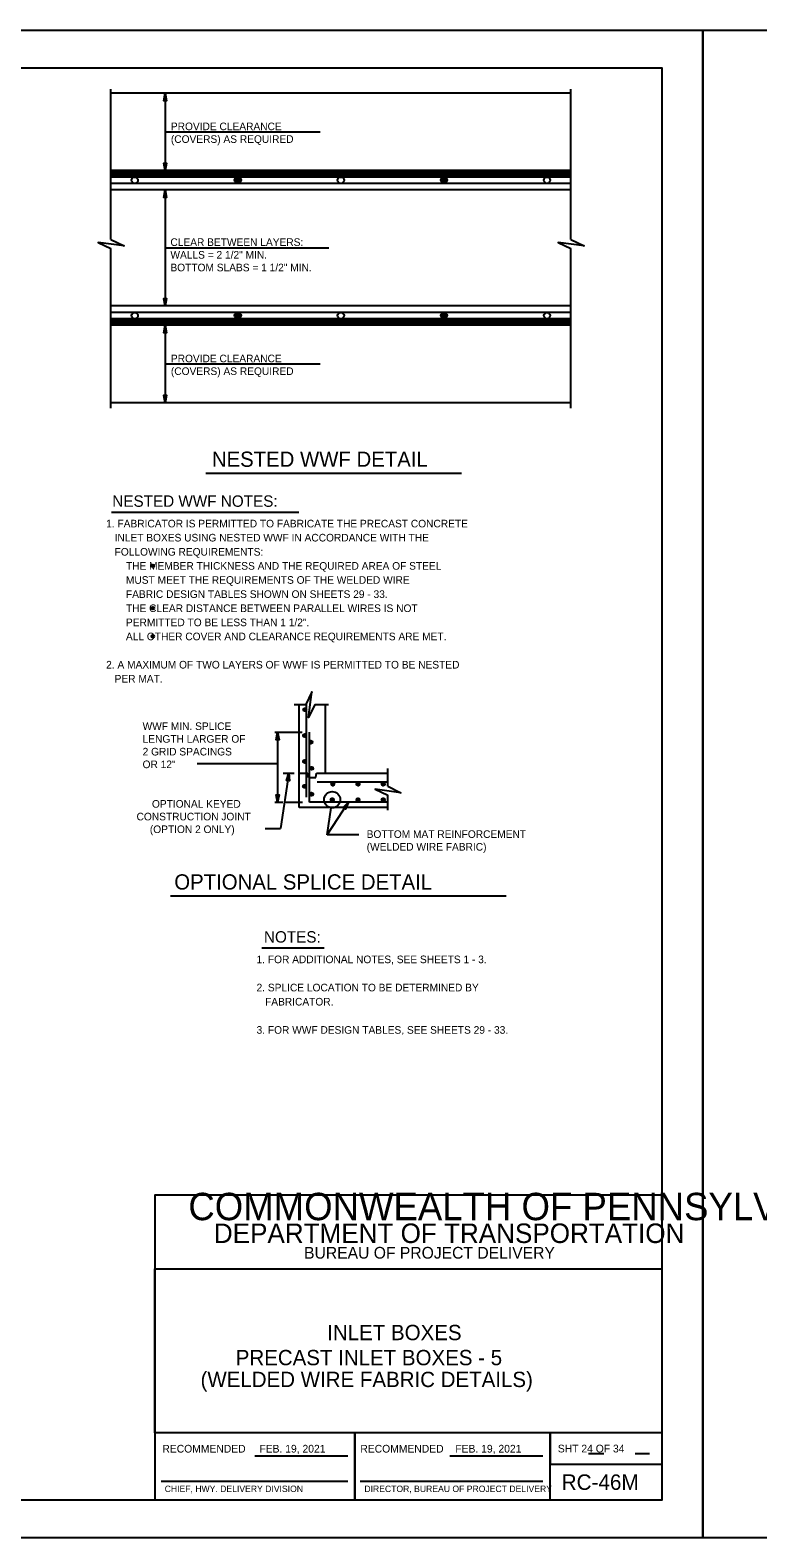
# Model space of a CAD drawing. Extents: x -6420 to 49575, y -4552 to 11624.
# Drawn here: x 6505 to 7447, y 1880 to 3829 of the extents above; entities that cross this region are included whole.
import ezdxf

# ---------------------------------------------------------------- set-up
doc = ezdxf.new("R2010")
doc.units = 0
doc.layers.add('1', color=7, linetype='Continuous')
doc.layers.add('PLT-BNDY', color=7, linetype='Continuous')

msp = doc.modelspace()

# ---------------------------------------------------------------- linework, layer by layer
at = {"layer": '1'}
for p, q in [((6609.9, 3558), (6609.9, 3752.3)), ((7204.9, 3747.1), (6609.9, 3747.1)), ((6680, 3747.1), (6680, 3647.1)), ((7204.9, 3558), (7204.9, 3752.3)), ((6680, 3697.1), (6880.5, 3697.1)), ((7204.9, 3647.1), (6609.9, 3647.1)), ((7204.9, 3645.7), (6609.9, 3645.7)), ((7204.9, 3644.4), (6609.9, 3644.4)), ((7204.9, 3643), (6609.9, 3643)), ((7204.9, 3641.7), (6609.9, 3641.7)), ((7204.9, 3640.3), (6609.9, 3640.3)), ((7204.9, 3638.8), (6609.9, 3638.8)), ((7204.9, 3630.5), (6609.9, 3630.5)), ((7204.9, 3622.1), (6609.9, 3622.1)), ((6680, 3622.1), (6680, 3472.1)), ((6680, 3547.1), (6891.7, 3547.1)), ((6609.9, 3340.1), (6609.9, 3546.5)), ((7204.9, 3340.1), (7204.9, 3546.5)), ((7204.9, 3472.1), (6609.9, 3472.1)), ((7204.9, 3463.7), (6609.9, 3463.7)), ((7204.9, 3455.4), (6609.9, 3455.4)), ((7204.9, 3453.9), (6609.9, 3453.9)), ((7204.9, 3452.5), (6609.9, 3452.5)), ((7204.9, 3451.2), (6609.9, 3451.2)), ((7204.9, 3449.8), (6609.9, 3449.8)), ((7204.9, 3448.5), (6609.9, 3448.5)), ((7204.9, 3447.1), (6609.9, 3447.1)), ((6680, 3447.1), (6680, 3347.1)), ((6680, 3397.1), (6880.5, 3397.1)), ((7204.9, 3347.1), (6609.9, 3347.1)), ((6732.5, 3255.9), (7063.6, 3255.9)), ((6610.7, 3205.7), (6853, 3205.7)), ((6847.1, 2957.1), (6862.2, 2957.1)), ((6853.6, 2823.7), (6853.6, 2957.1)), ((6863, 2837), (6863, 2958.8)), ((6873.7, 2957.1), (6891.3, 2957.1)), ((6886.9, 2957.1), (6886.9, 2868.2)), ((6822.1, 2921.3), (6857.3, 2921.3)), ((6825.5, 2921.3), (6825.5, 2830.6)), ((6867, 2830.6), (6867, 2921.3)), ((6721.6, 2880.9), (6825.5, 2880.9)), ((6840.2, 2868.2), (6829.3, 2796.5)), ((6832.9, 2868.2), (6847.2, 2868.2)), ((6853.5, 2868.2), (6864.7, 2868.2)), ((6865.4, 2862.6), (6864.7, 2868.2)), ((6875.1, 2862.6), (6875.8, 2868.2)), ((6875.8, 2868.2), (6886.9, 2868.2)), ((6886.9, 2868.2), (6968.2, 2868.2)), ((6968.2, 2851.3), (6968.2, 2874.4)), ((6865.4, 2862.6), (6875.1, 2862.6)), ((6876.9, 2857), (6968.2, 2857)), ((6822.1, 2830.6), (6832.3, 2830.6)), ((6836.2, 2830.6), (6857.8, 2830.6)), ((6968.2, 2830.6), (6867, 2830.6)), ((6889.6, 2788.6), (6917.2, 2830.6)), ((6896.2, 2833.9), (6896.2, 2833.9)), ((6968.2, 2820.2), (6968.2, 2839.8)), ((6968.2, 2823.7), (6853.6, 2823.7)), ((6889.6, 2788.6), (6894.8, 2823.5)), ((6809.3, 2796.5), (6829.3, 2796.5)), ((6930.8, 2788.6), (6889.6, 2788.6)), ((6686.8, 2709.5), (7121.4, 2709.5)), ((6805.3, 2642.4), (6885.7, 2642.4)), ((7227.6, 1988.7), (7247.7, 1988.7)), ((7288, 1988.7), (7306.8, 1988.7)), ((6795.9, 1986), (6916.3, 1986)), ((7048.5, 1986), (7168.9, 1986)), ((6674.8, 1953), (6916.3, 1953)), ((6932.4, 1953), (7168.9, 1953))]:
    msp.add_line(p, q, dxfattribs=at)
for points in [[(7323.1, 1929), (7323.1, 3779.4), (4744.3, 3779.4), (4744.3, 1929), (7323.1, 1929), (7323.1, 2015.5), (6666.9, 2015.5), (6666.9, 2227.7), (7323.1, 2227.7), (7323.1, 2322.7), (6666.9, 2322.7), (6666.9, 1929), (6925.4, 1929), (6925.4, 2015.5), (6925.4, 1929), (7178.1, 1929), (7178.1, 2015.5), (7178.1, 1975.1), (7323.1, 1975.1)], [(6680, 3747.1), (6681.9, 3737.3), (6681.6, 3737.7), (6681.3, 3738.1), (6681, 3738.3), (6680.7, 3738.5), (6680.4, 3738.5), (6680, 3738.6), (6679.7, 3738.5), (6679.4, 3738.5), (6679, 3738.3), (6678.7, 3738.1), (6678.5, 3737.7), (6678.2, 3737.3), (6680, 3747.1), (6678.5, 3737.7), (6678.7, 3738.1), (6680, 3747.1), (6679, 3738.3), (6679.4, 3738.5), (6680, 3747.1), (6679.7, 3738.5), (6680, 3738.6), (6680, 3747.1), (6680.4, 3738.5), (6680.7, 3738.5), (6680, 3747.1), (6681, 3738.3), (6681.3, 3738.1), (6680, 3747.1), (6681.6, 3737.7)], [(6680, 3647.1), (6678.2, 3656.9), (6678.5, 3656.5), (6678.7, 3656.1), (6679, 3655.9), (6679.4, 3655.7), (6679.7, 3655.7), (6680, 3655.6), (6680.4, 3655.7), (6680.7, 3655.7), (6681, 3655.9), (6681.3, 3656.1), (6681.6, 3656.5), (6681.9, 3656.9), (6680, 3647.1), (6681.6, 3656.5), (6681.3, 3656.1), (6680, 3647.1), (6681, 3655.9), (6680.7, 3655.7), (6680, 3647.1), (6680.4, 3655.7), (6680, 3655.6), (6680, 3647.1), (6679.7, 3655.7), (6679.4, 3655.7), (6680, 3647.1), (6679, 3655.9), (6678.7, 3656.1), (6680, 3647.1), (6678.5, 3656.5)], [(6680, 3622.1), (6681.9, 3612.4), (6681.6, 3612.7), (6681.3, 3613.1), (6681, 3613.3), (6680.7, 3613.5), (6680.4, 3613.6), (6680, 3613.6), (6679.7, 3613.6), (6679.4, 3613.5), (6679, 3613.3), (6678.7, 3613.1), (6678.5, 3612.7), (6678.2, 3612.4), (6680, 3622.1), (6678.5, 3612.7), (6678.7, 3613.1), (6680, 3622.1), (6679, 3613.3), (6679.4, 3613.5), (6680, 3622.1), (6679.7, 3613.6), (6680, 3613.6), (6680, 3622.1), (6680.4, 3613.6), (6680.7, 3613.5), (6680, 3622.1), (6681, 3613.3), (6681.3, 3613.1), (6680, 3622.1), (6681.6, 3612.7)], [(6609.9, 3558), (6626.9, 3549.7), (6593.6, 3554.2), (6609.9, 3546.5)], [(7204.9, 3558), (7222, 3549.7), (7188.7, 3554.2), (7204.9, 3546.5)], [(6680, 3472.1), (6678.2, 3481.8), (6678.5, 3481.5), (6678.7, 3481.1), (6679, 3480.9), (6679.4, 3480.7), (6679.7, 3480.6), (6680, 3480.6), (6680.4, 3480.6), (6680.7, 3480.7), (6681, 3480.9), (6681.3, 3481.1), (6681.6, 3481.5), (6681.9, 3481.8), (6680, 3472.1), (6681.6, 3481.5), (6681.3, 3481.1), (6680, 3472.1), (6681, 3480.9), (6680.7, 3480.7), (6680, 3472.1), (6680.4, 3480.6), (6680, 3480.6), (6680, 3472.1), (6679.7, 3480.6), (6679.4, 3480.7), (6680, 3472.1), (6679, 3480.9), (6678.7, 3481.1), (6680, 3472.1), (6678.5, 3481.5)], [(6680, 3447.1), (6681.9, 3437.3), (6681.6, 3437.7), (6681.3, 3438.1), (6681, 3438.3), (6680.7, 3438.5), (6680.4, 3438.5), (6680, 3438.6), (6679.7, 3438.5), (6679.4, 3438.5), (6679, 3438.3), (6678.7, 3438.1), (6678.5, 3437.7), (6678.2, 3437.3), (6680, 3447.1), (6678.5, 3437.7), (6678.7, 3438.1), (6680, 3447.1), (6679, 3438.3), (6679.4, 3438.5), (6680, 3447.1), (6679.7, 3438.5), (6680, 3438.6), (6680, 3447.1), (6680.4, 3438.5), (6680.7, 3438.5), (6680, 3447.1), (6681, 3438.3), (6681.3, 3438.1), (6680, 3447.1), (6681.6, 3437.7)], [(6680, 3347.1), (6678.2, 3356.9), (6678.5, 3356.5), (6678.7, 3356.1), (6679, 3355.9), (6679.4, 3355.7), (6679.7, 3355.7), (6680, 3355.6), (6680.4, 3355.7), (6680.7, 3355.7), (6681, 3355.9), (6681.3, 3356.1), (6681.6, 3356.5), (6681.9, 3356.9), (6680, 3347.1), (6681.6, 3356.5), (6681.3, 3356.1), (6680, 3347.1), (6681, 3355.9), (6680.7, 3355.7), (6680, 3347.1), (6680.4, 3355.7), (6680, 3355.6), (6680, 3347.1), (6679.7, 3355.7), (6679.4, 3355.7), (6680, 3347.1), (6679, 3355.9), (6678.7, 3356.1), (6680, 3347.1), (6678.5, 3356.5)], [(6873.7, 2957.1), (6865.4, 2940.1), (6869.9, 2973.4), (6862.2, 2957.1)], [(6825.5, 2921.3), (6827.4, 2911.5), (6827.1, 2911.8), (6826.8, 2912.2), (6826.5, 2912.4), (6826.2, 2912.6), (6825.8, 2912.7), (6825.5, 2912.7), (6825.2, 2912.7), (6824.9, 2912.6), (6824.5, 2912.4), (6824.2, 2912.2), (6823.9, 2911.8), (6823.7, 2911.5), (6825.5, 2921.3), (6823.9, 2911.8), (6824.2, 2912.2), (6825.5, 2921.3), (6824.5, 2912.4), (6824.9, 2912.6), (6825.5, 2921.3), (6825.2, 2912.7), (6825.5, 2912.7), (6825.5, 2921.3), (6825.8, 2912.7), (6826.2, 2912.6), (6825.5, 2921.3), (6826.5, 2912.4), (6826.8, 2912.2), (6825.5, 2921.3), (6827.1, 2911.8)], [(6840.2, 2868.2), (6840.8, 2858.3), (6840.6, 2858.7), (6840.4, 2859.1), (6840.1, 2859.3), (6839.8, 2859.6), (6839.5, 2859.7), (6839.1, 2859.8), (6838.8, 2859.8), (6838.5, 2859.7), (6838.1, 2859.6), (6837.8, 2859.4), (6837.5, 2859.1), (6837.2, 2858.8), (6840.2, 2868.2), (6837.5, 2859.1), (6837.8, 2859.4), (6840.2, 2868.2), (6838.1, 2859.6), (6838.5, 2859.7), (6840.2, 2868.2), (6838.8, 2859.8), (6839.1, 2859.8), (6840.2, 2868.2), (6839.5, 2859.7), (6839.8, 2859.6), (6840.2, 2868.2), (6840.1, 2859.3), (6840.4, 2859.1), (6840.2, 2868.2), (6840.6, 2858.7)], [(6968.2, 2851.3), (6985.2, 2843), (6951.9, 2847.5), (6968.2, 2839.8)], [(6825.5, 2830.6), (6823.7, 2840.4), (6823.9, 2840), (6824.2, 2839.6), (6824.5, 2839.4), (6824.9, 2839.2), (6825.2, 2839.2), (6825.5, 2839.1), (6825.8, 2839.2), (6826.2, 2839.2), (6826.5, 2839.4), (6826.8, 2839.6), (6827.1, 2840), (6827.4, 2840.4), (6825.5, 2830.6), (6827.1, 2840), (6826.8, 2839.6), (6825.5, 2830.6), (6826.5, 2839.4), (6826.2, 2839.2), (6825.5, 2830.6), (6825.8, 2839.2), (6825.5, 2839.1), (6825.5, 2830.6), (6825.2, 2839.2), (6824.9, 2839.2), (6825.5, 2830.6), (6824.5, 2839.4), (6824.2, 2839.6), (6825.5, 2830.6), (6823.9, 2840)], [(6917.2, 2830.6), (6913.2, 2821.5), (6913.2, 2821.9), (6913.2, 2822.4), (6913.1, 2822.7), (6912.9, 2823.1), (6912.7, 2823.3), (6912.4, 2823.6), (6912.1, 2823.7), (6911.8, 2823.8), (6911.4, 2823.9), (6911.1, 2823.9), (6910.6, 2823.7), (6910.2, 2823.5), (6917.2, 2830.6), (6910.6, 2823.7), (6911.1, 2823.9), (6917.2, 2830.6), (6911.4, 2823.9), (6911.8, 2823.8), (6917.2, 2830.6), (6912.1, 2823.7), (6912.4, 2823.6), (6917.2, 2830.6), (6912.7, 2823.3), (6912.9, 2823.1), (6917.2, 2830.6), (6913.1, 2822.7), (6913.2, 2822.4), (6917.2, 2830.6), (6913.2, 2821.9)]]:
    msp.add_lwpolyline(points, dxfattribs=at)
for centre, radius in [((6640.7, 3634.6), 4.16), ((6774.1, 3634.6), 4.16), ((6774.1, 3634.6), 3.36), ((6774.1, 3634.6), 2.56), ((6774.1, 3634.6), 1.76), ((6774.1, 3634.6), 0.96), ((6907.4, 3634.6), 4.16), ((7040.8, 3634.6), 4.16), ((7040.8, 3634.6), 3.36), ((7040.8, 3634.6), 2.56), ((7040.8, 3634.6), 1.76), ((7040.8, 3634.6), 0.96), ((7174.1, 3634.6), 4.16), ((6640.7, 3459.6), 4.16), ((6774.1, 3459.6), 4.16), ((6774.1, 3459.6), 3.36), ((6774.1, 3459.6), 2.56), ((6774.1, 3459.6), 1.76), ((6774.1, 3459.6), 0.96), ((6907.4, 3459.6), 4.16), ((7040.8, 3459.6), 4.16), ((7040.8, 3459.6), 3.36), ((7040.8, 3459.6), 2.56), ((7040.8, 3459.6), 1.76), ((7040.8, 3459.6), 0.96), ((7174.1, 3459.6), 4.16), ((6664.1, 3136.3), 1.75), ((6664.1, 3136.3), 1.31), ((6664.1, 3136.3), 0.875), ((6664.1, 3136.3), 0.437), ((6664.1, 3081.6), 1.75), ((6664.1, 3081.6), 1.31), ((6664.1, 3081.6), 0.875), ((6664.1, 3081.6), 0.437), ((6664.1, 3045.1), 1.75), ((6664.1, 3045.1), 1.31), ((6664.1, 3045.1), 0.875), ((6664.1, 3045.1), 0.437), ((6860.8, 2950.3), 2.08), ((6860.8, 2950.3), 1.94), ((6860.8, 2950.3), 1.79), ((6860.8, 2950.3), 1.64), ((6860.8, 2950.3), 1.49), ((6860.8, 2950.3), 1.34), ((6860.8, 2950.3), 1.2), ((6860.8, 2950.3), 1.05), ((6860.8, 2950.3), 0.9), ((6860.8, 2950.3), 0.752), ((6860.8, 2950.3), 0.604), ((6860.8, 2950.3), 0.456), ((6860.8, 2950.3), 0.308), ((6860.8, 2950.3), 0.16), ((6860.6, 2916.8), 2.08), ((6860.6, 2916.8), 1.94), ((6860.6, 2916.8), 1.79), ((6860.6, 2916.8), 1.64), ((6860.6, 2916.8), 1.49), ((6860.6, 2916.8), 1.34), ((6860.6, 2916.8), 1.2), ((6860.6, 2916.8), 1.05), ((6860.6, 2916.8), 0.9), ((6860.6, 2916.8), 0.752), ((6860.6, 2916.8), 0.604), ((6860.6, 2916.8), 0.456), ((6860.6, 2916.8), 0.308), ((6860.6, 2916.8), 0.16), ((6868.7, 2908.3), 2.08), ((6868.7, 2908.3), 1.94), ((6868.7, 2908.3), 1.79), ((6868.7, 2908.3), 1.64), ((6868.7, 2908.3), 1.49), ((6868.7, 2908.3), 1.34), ((6868.7, 2908.3), 1.2), ((6868.7, 2908.3), 1.05), ((6868.7, 2908.3), 0.9), ((6868.7, 2908.3), 0.752), ((6868.7, 2908.3), 0.604), ((6868.7, 2908.3), 0.456), ((6868.7, 2908.3), 0.308), ((6868.7, 2908.3), 0.16), ((6860.6, 2883.4), 2.08), ((6860.6, 2883.4), 1.94), ((6860.6, 2883.4), 1.79), ((6860.6, 2883.4), 1.64), ((6860.6, 2883.4), 1.49), ((6860.6, 2883.4), 1.34), ((6860.6, 2883.4), 1.2), ((6860.6, 2883.4), 1.05), ((6860.6, 2883.4), 0.9), ((6860.6, 2883.4), 0.752), ((6860.6, 2883.4), 0.604), ((6860.6, 2883.4), 0.456), ((6860.6, 2883.4), 0.308), ((6860.6, 2883.4), 0.16), ((6869.6, 2874.4), 2.08), ((6869.6, 2874.4), 1.94), ((6869.6, 2874.4), 1.79), ((6869.6, 2874.4), 1.64), ((6869.6, 2874.4), 1.49), ((6869.6, 2874.4), 1.34), ((6869.6, 2874.4), 1.2), ((6869.6, 2874.4), 1.05), ((6869.6, 2874.4), 0.9), ((6869.6, 2874.4), 0.752), ((6869.6, 2874.4), 0.604), ((6869.6, 2874.4), 0.456), ((6869.6, 2874.4), 0.308), ((6869.6, 2874.4), 0.16), ((6860.4, 2851.2), 2.08), ((6860.4, 2851.2), 1.94), ((6860.4, 2851.2), 1.79), ((6860.4, 2851.2), 1.64), ((6860.4, 2851.2), 1.49), ((6860.4, 2851.2), 1.34), ((6860.4, 2851.2), 1.2), ((6860.4, 2851.2), 1.05), ((6860.4, 2851.2), 0.9), ((6860.4, 2851.2), 0.752), ((6860.4, 2851.2), 0.604), ((6860.4, 2851.2), 0.456), ((6860.4, 2851.2), 0.308), ((6860.4, 2851.2), 0.16), ((6897, 2854.1), 2.08), ((6897, 2854.1), 1.94), ((6897, 2854.1), 1.79), ((6897, 2854.1), 1.64), ((6897, 2854.1), 1.49), ((6897, 2854.1), 1.34), ((6897, 2854.1), 1.2), ((6897, 2854.1), 1.05), ((6897, 2854.1), 0.9), ((6897, 2854.1), 0.752), ((6897, 2854.1), 0.604), ((6897, 2854.1), 0.456), ((6897, 2854.1), 0.308), ((6897, 2854.1), 0.16), ((6929.6, 2854.1), 2.08), ((6929.6, 2854.1), 1.94), ((6929.6, 2854.1), 1.79), ((6929.6, 2854.1), 1.64), ((6929.6, 2854.1), 1.49), ((6929.6, 2854.1), 1.34), ((6929.6, 2854.1), 1.2), ((6929.6, 2854.1), 1.05), ((6929.6, 2854.1), 0.9), ((6929.6, 2854.1), 0.752), ((6929.6, 2854.1), 0.604), ((6929.6, 2854.1), 0.456), ((6929.6, 2854.1), 0.308), ((6929.6, 2854.1), 0.16), ((6962.2, 2854.1), 2.08), ((6962.2, 2854.1), 1.94), ((6962.2, 2854.1), 1.79), ((6962.2, 2854.1), 1.64), ((6962.2, 2854.1), 1.49), ((6962.2, 2854.1), 1.34), ((6962.2, 2854.1), 1.2), ((6962.2, 2854.1), 1.05), ((6962.2, 2854.1), 0.9), ((6962.2, 2854.1), 0.752), ((6962.2, 2854.1), 0.604), ((6962.2, 2854.1), 0.456), ((6962.2, 2854.1), 0.308), ((6962.2, 2854.1), 0.16), ((6869.6, 2841), 2.08), ((6869.6, 2841), 1.94), ((6869.6, 2841), 1.79), ((6869.6, 2841), 1.64), ((6869.6, 2841), 1.49), ((6869.6, 2841), 1.34), ((6869.6, 2841), 1.2), ((6869.6, 2841), 1.05), ((6869.6, 2841), 0.9), ((6869.6, 2841), 0.752), ((6869.6, 2841), 0.604), ((6869.6, 2841), 0.456), ((6869.6, 2841), 0.308), ((6869.6, 2841), 0.16), ((6896.2, 2833.9), 10.5), ((6896.2, 2833.9), 2.08), ((6896.2, 2833.9), 1.94), ((6896.2, 2833.9), 1.79), ((6896.2, 2833.9), 1.64), ((6896.2, 2833.9), 1.49), ((6896.2, 2833.9), 1.34), ((6896.2, 2833.9), 1.2), ((6896.2, 2833.9), 1.05), ((6896.2, 2833.9), 0.9), ((6896.2, 2833.9), 0.752), ((6896.2, 2833.9), 0.604), ((6896.2, 2833.9), 0.456), ((6896.2, 2833.9), 0.308), ((6896.2, 2833.9), 0.16), ((6929.6, 2833.9), 2.08), ((6929.6, 2833.9), 1.94), ((6929.6, 2833.9), 1.79), ((6929.6, 2833.9), 1.64), ((6929.6, 2833.9), 1.49), ((6929.6, 2833.9), 1.34), ((6929.6, 2833.9), 1.2), ((6929.6, 2833.9), 1.05), ((6929.6, 2833.9), 0.9), ((6929.6, 2833.9), 0.752), ((6929.6, 2833.9), 0.604), ((6929.6, 2833.9), 0.456), ((6929.6, 2833.9), 0.308), ((6929.6, 2833.9), 0.16), ((6962.2, 2833.9), 2.08), ((6962.2, 2833.9), 1.94), ((6962.2, 2833.9), 1.79), ((6962.2, 2833.9), 1.64), ((6962.2, 2833.9), 1.49), ((6962.2, 2833.9), 1.34), ((6962.2, 2833.9), 1.2), ((6962.2, 2833.9), 1.05), ((6962.2, 2833.9), 0.9), ((6962.2, 2833.9), 0.752), ((6962.2, 2833.9), 0.604), ((6962.2, 2833.9), 0.456), ((6962.2, 2833.9), 0.308), ((6962.2, 2833.9), 0.16)]:
    msp.add_circle(centre, radius, dxfattribs=at)
at = {"layer": 'PLT-BNDY'}
for points in [[(4616.4, 3828.6), (7375.6, 3828.6), (7375.6, 1879.8), (4616.4, 1879.8)], [(7375.6, 3828.6), (10134.8, 3828.6), (10134.8, 1879.8), (7375.6, 1879.8)]]:
    msp.add_lwpolyline(points, close=True, dxfattribs=at)

# ---------------------------------------------------------------- texts
at = {"layer": '1'}
for s, height, p in [('PROVIDE CLEARANCE', 9.843, (6687.5, 3699.3)), ('(COVERS) AS REQUIRED', 9.843, (6687.5, 3682.9)), ('CLEAR BETWEEN LAYERS:', 9.843, (6686.9, 3549.7)), ('WALLS = 2 1/2" MIN.', 9.843, (6686.9, 3533.3)), ('BOTTOM SLABS = 1 1/2" MIN.', 9.843, (6686.9, 3516.9)), ('(COVERS) AS REQUIRED', 9.843, (6687.5, 3382.9)), ('PROVIDE CLEARANCE', 9.843, (6687.5, 3399.3)), ('NESTED WWF DETAIL', 19.685, (6740.5, 3264.2)), ('NESTED WWF NOTES:', 14.764, (6611.7, 3212.5)), (' 1. FABRICATOR IS PERMITTED TO FABRICATE THE PRECAST CONCRETE', 9.843, (6600.1, 3185.9)), ('    INLET BOXES USING NESTED WWF IN ACCORDANCE WITH THE', 9.843, (6600.1, 3167.7)), ('    FOLLOWING REQUIREMENTS:', 9.843, (6600.1, 3149.4)), ('        THE MEMBER THICKNESS AND THE REQUIRED AREA OF STEEL', 9.843, (6600.1, 3131.2)), ('        MUST MEET THE REQUIREMENTS OF THE WELDED WIRE', 9.843, (6600.1, 3113)), ('        FABRIC DESIGN TABLES SHOWN ON SHEETS 29 - 33.', 9.843, (6600.1, 3094.7)), ('        THE CLEAR DISTANCE BETWEEN PARALLEL WIRES IS NOT', 9.843, (6600.1, 3076.5)), ('        PERMITTED TO BE LESS THAN 1 1/2".', 9.843, (6600.1, 3058.2)), ('        ALL OTHER COVER AND CLEARANCE REQUIREMENTS ARE MET.', 9.843, (6600.1, 3040)), (' 2. A MAXIMUM OF TWO LAYERS OF WWF IS PERMITTED TO BE NESTED', 9.843, (6600.1, 3003.5)), ('    PER MAT.', 9.843, (6600.1, 2985.3)), ('WWF MIN. SPLICE', 9.843, (6650.9, 2924)), ('LENGTH LARGER OF', 9.843, (6650.9, 2907.6)), ('2 GRID SPACINGS', 9.843, (6650.9, 2891.1)), ('OR 12"', 9.84, (6650.9, 2874.7)), ('OPTIONAL KEYED', 9.843, (6663, 2823.6)), ('CONSTRUCTION JOINT', 9.843, (6643.1, 2807.2)), ('(OPTION 2 ONLY)', 9.843, (6660.3, 2790.8)), ('BOTTOM MAT REINFORCEMENT', 9.843, (6940.8, 2784.5)), ('(WELDED WIRE FABRIC)', 9.843, (6940.8, 2768.1)), ('OPTIONAL SPLICE DETAIL', 19.685, (6691.9, 2717.8)), ('NOTES:', 14.76, (6807.9, 2649.2)), (' 1. FOR ADDITIONAL NOTES, SEE SHEETS 1 - 3.', 9.843, (6794.7, 2622.6)), (' 2. SPLICE LOCATION TO BE DETERMINED BY', 9.843, (6794.7, 2586.2)), ('    FABRICATOR.', 9.843, (6794.7, 2567.9)), (' 3. FOR WWF DESIGN TABLES, SEE SHEETS 29 - 33.', 9.843, (6794.7, 2531.4)), ('COMMONWEALTH OF PENNSYLVANIA', 35.379, (6710.1, 2290.4)), ('DEPARTMENT OF TRANSPORTATION', 25.211, (6743.1, 2260.9)), ('BUREAU OF PROJECT DELIVERY', 15.164, (6859.8, 2240.7)), ('INLET BOXES', 19.816, (6889.8, 2135.3)), ('PRECAST INLET BOXES - 5', 19.816, (6771.4, 2102.9)), ('(WELDED WIRE FABRIC DETAILS)', 19.816, (6725.9, 2074.7)), ('RECOMMENDED', 10, (6676.5, 1990)), ('FEB. 19, 2021', 10, (6802, 1990)), ('RECOMMENDED', 10, (6932.6, 1990)), ('FEB. 19, 2021', 10, (7055.5, 1990)), ('SHT 24 OF 34', 10, (7188.1, 1990.2)), ('RC-46M', 20, (7193.1, 1941.8)), ('CHIEF, HWY. DELIVERY DIVISION', 8.333, (6679.5, 1939)), ('DIRECTOR, BUREAU OF PROJECT DELIVERY', 8.333, (6937.8, 1939))]:
    msp.add_text(s, height=height, dxfattribs=at).set_placement(p)

doc.saveas('drawing.dxf')
